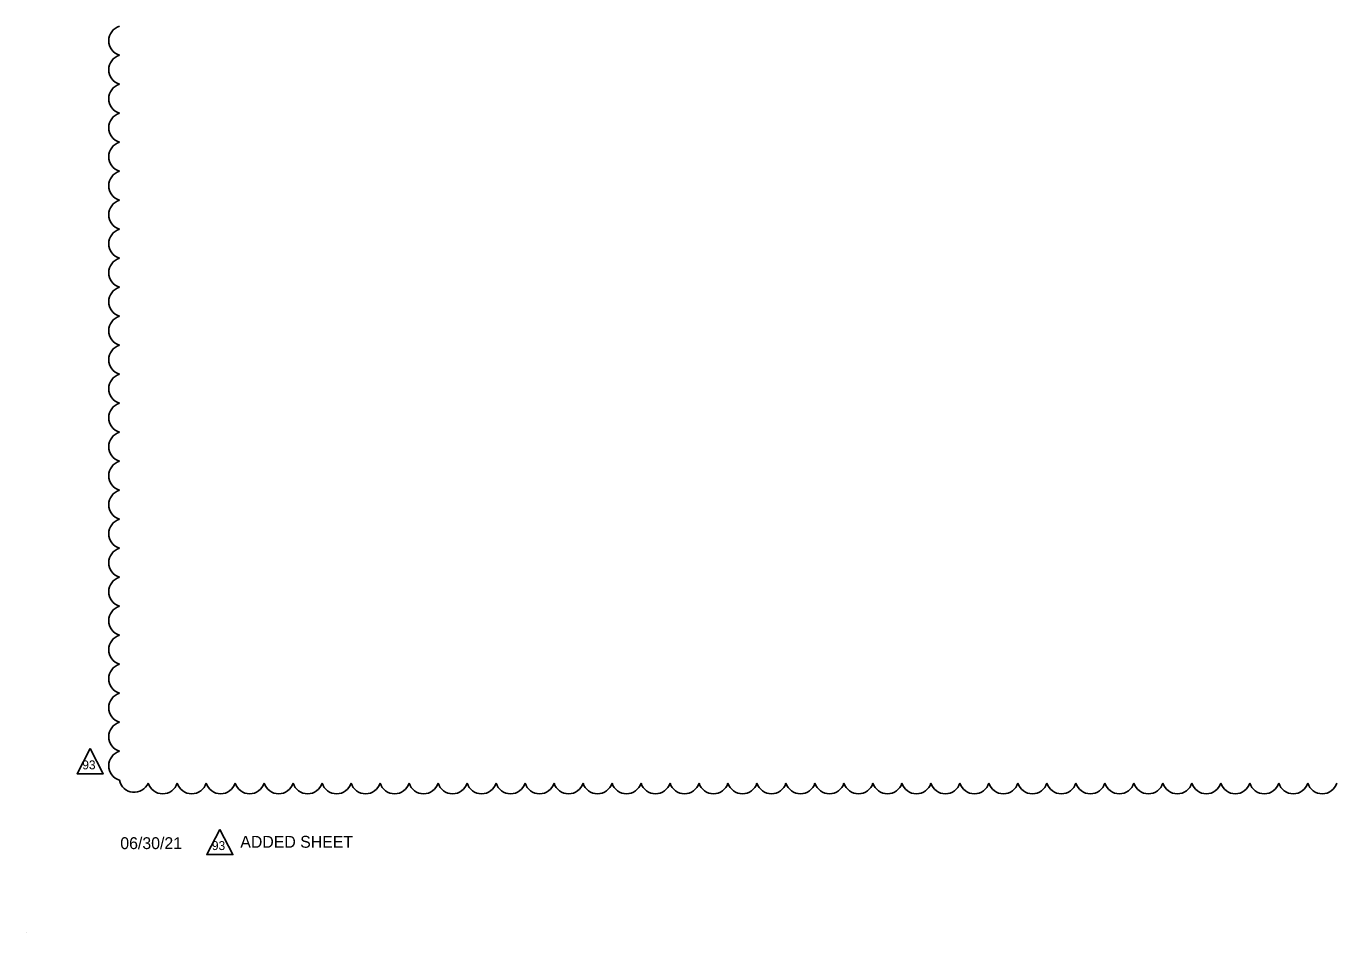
# Model space of a CAD drawing. Extents: x -811 to -790, y -2284 to -2178.
# Drawn here: x -811.34 to -803.6, y -2230.16 to -2224.81 of the extents above; entities that cross this region are included whole.
import ezdxf

# ---------------------------------------------------------------- set-up
doc = ezdxf.new("R2010")
doc.units = 0
for name, color, linetype in [('SheetBorder_dp', 7, 'Continuous'), ('TextMisc', 7, 'Continuous'), ('TextTitle', 7, 'Continuous')]:
    doc.layers.add(name, color=color, linetype=linetype)

msp = doc.modelspace()

# ---------------------------------------------------------------- linework, layer by layer
at = {"layer": 'SheetBorder_dp'}
msp.add_line((-811.3358, -2230.1628), (-811.3358, -2230.1628), dxfattribs=at)
at = {"layer": 'TextMisc'}
for points in [[(-810.9581, -2229.0764), (-811.0351, -2229.2247), (-810.8811, -2229.2247)], [(-810.1928, -2229.5528), (-810.2698, -2229.7012), (-810.1158, -2229.7012)]]:
    msp.add_lwpolyline(points, close=True, dxfattribs=at)
at = {"layer": 'TextTitle'}
for centre, radius, start, end in [((-810.7588, -2224.8992), 0.0897, 107.5, 252.5), ((-810.7588, -2225.0703), 0.0897, 107.5, 252.5), ((-810.7588, -2225.2415), 0.0897, 107.5, 252.5), ((-810.7588, -2225.4126), 0.0897, 107.5, 252.5), ((-810.7588, -2225.5837), 0.0897, 107.5, 252.5), ((-810.7588, -2225.7548), 0.0897, 107.5, 252.5), ((-810.7588, -2225.926), 0.0897, 107.5, 252.5), ((-810.7588, -2226.0971), 0.0897, 107.5, 252.5), ((-810.7588, -2226.2682), 0.0897, 107.5, 252.5), ((-810.7588, -2226.4393), 0.0897, 107.5, 252.5), ((-810.7588, -2226.6104), 0.0897, 107.5, 252.5), ((-810.7588, -2226.7816), 0.0897, 107.5, 252.5), ((-810.7588, -2226.9527), 0.0897, 107.5, 252.5), ((-810.7588, -2227.1238), 0.0897, 107.5, 252.5), ((-810.7588, -2227.2949), 0.0897, 107.5, 252.5), ((-810.7588, -2227.4661), 0.0897, 107.5, 252.5), ((-810.7588, -2227.6372), 0.0897, 107.5, 252.5), ((-810.7588, -2227.8083), 0.0897, 107.5, 252.5), ((-810.7588, -2227.9794), 0.0897, 107.5, 252.5), ((-810.7588, -2228.1505), 0.0897, 107.5, 252.5), ((-810.7588, -2228.3217), 0.0897, 107.5, 252.5), ((-810.7588, -2228.4928), 0.0897, 107.5, 252.5), ((-810.7588, -2228.6639), 0.0897, 107.5, 252.5), ((-810.7588, -2228.835), 0.0897, 107.5, 252.5), ((-810.7588, -2229.0062), 0.0897, 107.5, 252.5), ((-810.7588, -2229.1773), 0.0897, 107.5, 252.5), ((-810.698, -2229.2446), 0.0896, 191.74536, 336.74536), ((-810.5301, -2229.253), 0.0897, 197.5, 342.5), ((-810.359, -2229.253), 0.0897, 197.5, 342.5), ((-810.1879, -2229.253), 0.0897, 197.5, 342.5), ((-810.0167, -2229.253), 0.0897, 197.5, 342.5), ((-809.8456, -2229.253), 0.0897, 197.5, 342.5), ((-809.6745, -2229.253), 0.0897, 197.5, 342.5), ((-809.5034, -2229.253), 0.0897, 197.5, 342.5), ((-809.3323, -2229.253), 0.0897, 197.5, 342.5), ((-809.1611, -2229.253), 0.0897, 197.5, 342.5), ((-808.99, -2229.253), 0.0897, 197.5, 342.5), ((-808.8189, -2229.253), 0.0897, 197.5, 342.5), ((-808.6478, -2229.253), 0.0897, 197.5, 342.5), ((-808.4766, -2229.253), 0.0897, 197.5, 342.5), ((-808.3055, -2229.253), 0.0897, 197.5, 342.5), ((-808.1344, -2229.253), 0.0897, 197.5, 342.5), ((-807.9633, -2229.253), 0.0897, 197.5, 342.5), ((-807.7921, -2229.253), 0.0897, 197.5, 342.5), ((-807.621, -2229.253), 0.0897, 197.5, 342.5), ((-807.4499, -2229.253), 0.0897, 197.5, 342.5), ((-807.2788, -2229.253), 0.0897, 197.5, 342.5), ((-807.1077, -2229.253), 0.0897, 197.5, 342.5), ((-806.9365, -2229.253), 0.0897, 197.5, 342.5), ((-806.7654, -2229.253), 0.0897, 197.5, 342.5), ((-806.5943, -2229.253), 0.0897, 197.5, 342.5), ((-806.4232, -2229.253), 0.0897, 197.5, 342.5), ((-806.252, -2229.253), 0.0897, 197.5, 342.5), ((-806.0809, -2229.253), 0.0897, 197.5, 342.5), ((-805.9098, -2229.253), 0.0897, 197.5, 342.5), ((-805.7387, -2229.253), 0.0897, 197.5, 342.5), ((-805.5676, -2229.253), 0.0897, 197.5, 342.5), ((-805.3964, -2229.253), 0.0897, 197.5, 342.5), ((-805.2253, -2229.253), 0.0897, 197.5, 342.5), ((-805.0542, -2229.253), 0.0897, 197.5, 342.5), ((-804.8831, -2229.253), 0.0897, 197.5, 342.5), ((-804.7119, -2229.253), 0.0897, 197.5, 342.5), ((-804.5408, -2229.253), 0.0897, 197.5, 342.5), ((-804.3697, -2229.253), 0.0897, 197.5, 342.5), ((-804.1986, -2229.253), 0.0897, 197.5, 342.5), ((-804.0275, -2229.253), 0.0897, 197.5, 342.5), ((-803.8563, -2229.253), 0.0897, 197.5, 342.5), ((-803.6852, -2229.253), 0.0897, 197.5, 342.5)]:
    msp.add_arc(centre, radius, start, end, dxfattribs=at)

# ---------------------------------------------------------------- texts
at = {"layer": 'TextMisc'}
for p in [(-811.0047, -2229.1984), (-810.2395, -2229.6748)]:
    msp.add_text('93', height=0.0525, rotation=360, dxfattribs=at).set_placement(p)
at = {"layer": 'TextTitle'}
for s, p in [('06/30/21', (-810.7803, -2229.6691)), ('ADDED SHEET', (-810.0721, -2229.661))]:
    msp.add_text(s, height=0.07, rotation=0, dxfattribs=at).set_placement(p)

doc.saveas('drawing.dxf')
